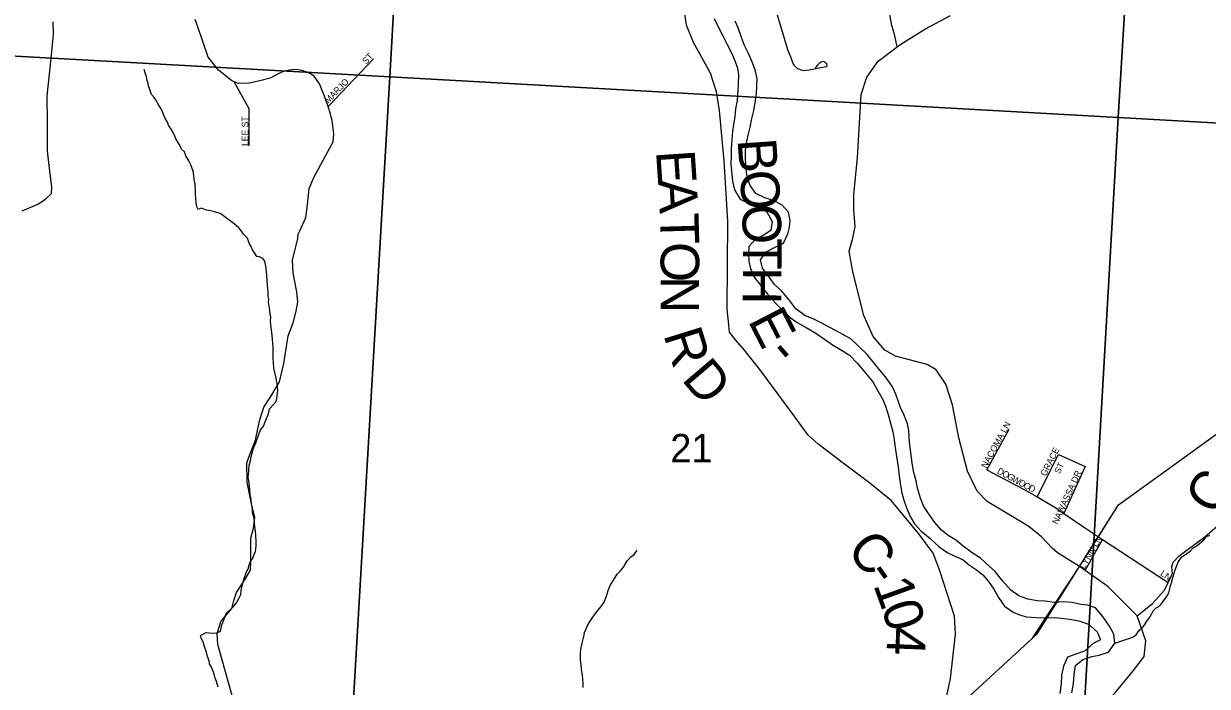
# Model space of a CAD drawing. Extents: x 0 to 34, y 0 to 22.
# Drawn here: x 4.174 to 5.915, y 17.152 to 18.127 of the extents above; entities that cross this region are included whole.
import ezdxf

# ---------------------------------------------------------------- set-up
doc = ezdxf.new("R2010")
doc.units = 0
for name, color, linetype in [('GM_P_State_Alignment', 7, 'Continuous'), ('GM_X_County_Road', 7, 'Continuous'), ('GM_X_County_Road_Text', 7, 'Continuous'), ('GM_X_Major_River', 7, 'Continuous'), ('GM_X_Minor_River', 7, 'Continuous'), ('GM_X_Section', 7, 'Continuous'), ('GM_X_Section_Text', 7, 'Continuous'), ('GM_X_Township_Road', 7, 'Continuous'), ('GM_X_Township_Subdivision', 7, 'Continuous'), ('GM_X_Township_Subdivision_Text', 7, 'Continuous'), ('SH_Data', 7, 'Continuous')]:
    doc.layers.add(name, color=color, linetype=linetype)

msp = doc.modelspace()

# ---------------------------------------------------------------- linework, layer by layer
at = {"layer": 'GM_P_State_Alignment'}
for points in [[(5.7539, 17.3702), (5.755, 17.3719), (5.7846, 17.4188), (6.0315, 17.5972), (6.2517, 17.7771), (6.3812, 17.906), (6.3923, 17.9142), (6.5211, 17.9881), (6.5265, 17.9911), (6.5405, 17.99), (6.6417, 17.9816), (6.6804, 17.9677), (6.7928, 17.9227), (6.8111, 17.9139), (6.95, 17.8445), (6.9564, 17.8413), (6.9734, 17.8302), (7.1338, 17.7232), (7.4175, 17.6454), (7.7316, 17.5623), (7.9253, 17.5014), (8.1533, 17.4614), (8.4655, 17.4165), (8.5004, 17.4073)], [(5.5533, 17.1267), (5.6581, 17.2228), (5.6649, 17.2291), (5.7272, 17.3279), (5.7539, 17.3702)]]:
    msp.add_lwpolyline(points, dxfattribs=at)
at = {"layer": 'GM_X_County_Road'}
for points in [[(5.2113, 17.6825), (5.2111, 17.6838), (5.2088, 17.7069), (5.2099, 17.836), (5.2042, 17.9248), (5.1973, 17.9992), (5.1928, 18.0265), (5.1844, 18.0542), (5.159, 18.099), (5.1491, 18.1244), (5.1438, 18.1574)], [(5.7687, 17.2984), (5.7353, 17.3221), (5.7272, 17.3279), (5.6949, 17.348), (5.687, 17.3548), (5.6714, 17.3715), (5.6528, 17.3867), (5.5914, 17.4235), (5.5766, 17.4387), (5.5622, 17.4683), (5.5497, 17.5176), (5.5402, 17.5658), (5.5307, 17.5962), (5.5163, 17.6175), (5.503, 17.6254), (5.4564, 17.6376), (5.4408, 17.6463), (5.4234, 17.6664), (5.4097, 17.6975), (5.3934, 17.7617), (5.3881, 17.792), (5.3937, 17.8114), (5.3971, 17.8285), (5.3949, 17.8531), (5.3949, 17.8748), (5.4005, 17.9298), (5.4058, 18.0228), (5.4141, 18.0483), (5.4311, 18.0714), (5.4591, 18.0925), (5.4645, 18.0965), (5.4994, 18.1185), (5.5373, 18.1387)], [(4.1716, 17.8515), (4.1944, 17.861), (4.2057, 17.8686), (4.2144, 17.877), (4.2151, 17.8865), (4.2116, 17.9137), (4.2087, 17.9395), (4.2085, 17.9814), (4.208, 18.0205), (4.2133, 18.0664), (4.2174, 18.1102), (4.2168, 18.1297)], [(5.8626, 17.3148), (5.864, 17.3177), (5.8632, 17.3276), (5.8651, 17.3344), (5.8738, 17.3436), (5.9117, 17.3717), (5.9375, 17.3945), (5.9761, 17.4302), (6.0004, 17.4477), (6.0284, 17.4572), (6.0584, 17.4599), (6.1057, 17.4713), (6.1402, 17.4976), (6.1663, 17.5242), (6.1951, 17.5504), (6.2021, 17.56), (6.2341, 17.6043), (6.269, 17.659), (6.2947, 17.6936), (6.3364, 17.7381), (6.3883, 17.7909), (6.4224, 17.8395), (6.444, 17.868), (6.4684, 17.8891)], [(5.5038, 17.0326), (5.5037, 17.0328), (5.4991, 17.0444), (5.5018, 17.0641), (5.5221, 17.1096), (5.5306, 17.131), (5.5374, 17.1633), (5.5449, 17.2286), (5.543, 17.2548), (5.5217, 17.3217), (5.5119, 17.3479), (5.4906, 17.3763), (5.4504, 17.4245), (5.4186, 17.4507), (5.3757, 17.4833), (5.342, 17.5084), (5.3279, 17.5213), (5.3082, 17.5482), (5.2581, 17.6162), (5.2342, 17.6462), (5.221, 17.6617), (5.2123, 17.6727), (5.2113, 17.6825)], [(5.8121, 17.2554), (5.8345, 17.2736), (5.8523, 17.293), (5.8577, 17.3045), (5.8626, 17.3148)], [(5.5775, 16.8401), (5.5775, 16.8401), (5.5917, 16.8644), (5.6126, 16.8982), (5.6436, 16.9499), (5.6671, 16.9898), (5.6894, 17.0263), (5.7152, 17.0673), (5.7402, 17.0981), (5.7815, 17.1445), (5.8068, 17.1749), (5.8224, 17.1954), (5.8246, 17.2189), (5.8121, 17.2554), (5.7704, 17.2971), (5.7687, 17.2983), (5.7687, 17.2984)]]:
    msp.add_lwpolyline(points, dxfattribs=at)
at = {"layer": 'GM_X_Major_River'}
for points in [[(5.1898, 18.1342), (5.1956, 18.1221), (5.2024, 18.1088), (5.2085, 18.0963), (5.215, 18.0838), (5.2207, 18.0713), (5.2237, 18.0611), (5.2253, 18.0516), (5.2249, 18.0384), (5.2242, 18.0285), (5.2235, 18.0137), (5.2212, 18.0016), (5.2198, 17.9898), (5.2179, 17.9784), (5.2168, 17.9682), (5.2157, 17.9564), (5.2146, 17.9431), (5.2146, 17.9325), (5.2143, 17.92), (5.2151, 17.9101), (5.2166, 17.895), (5.2197, 17.8821), (5.2277, 17.8688), (5.2402, 17.8628), (5.2531, 17.8579), (5.2671, 17.85), (5.2747, 17.8356), (5.2732, 17.8227), (5.2619, 17.815), (5.2513, 17.8105), (5.2407, 17.799), (5.24, 17.7884), (5.2408, 17.7767), (5.2431, 17.7664), (5.2484, 17.7539), (5.2587, 17.741), (5.2682, 17.7289), (5.28, 17.7157), (5.2895, 17.7058)], [(5.24, 18.0828), (5.2342, 18.0949), (5.23, 18.1063), (5.2251, 18.1207), (5.2205, 18.1305)], [(5.3799, 17.6689), (5.369, 17.675), (5.3588, 17.6802), (5.3489, 17.6855), (5.3361, 17.6919), (5.3232, 17.6972), (5.3099, 17.7074), (5.2993, 17.7211), (5.2886, 17.7335), (5.2784, 17.743), (5.2708, 17.7532), (5.2605, 17.7669), (5.2578, 17.7794), (5.2661, 17.7911), (5.2786, 17.7976), (5.2918, 17.8037), (5.2978, 17.8178), (5.3005, 17.8273), (5.3012, 17.8371), (5.2989, 17.8493), (5.2894, 17.8603), (5.2769, 17.8667), (5.264, 17.8704), (5.2507, 17.8768), (5.2424, 17.8886), (5.2382, 17.9011), (5.2366, 17.9132), (5.2358, 17.928), (5.2358, 17.9409), (5.2373, 17.9515), (5.2403, 17.9648), (5.2425, 17.9743), (5.2451, 17.9872), (5.2478, 17.999), (5.25, 18.0104), (5.2518, 18.024), (5.2526, 18.0343), (5.2529, 18.0456), (5.2499, 18.0589), (5.2449, 18.0714), (5.24, 18.0828)], [(5.2895, 17.7058), (5.3012, 17.6945), (5.3118, 17.6869), (5.3251, 17.6798), (5.3391, 17.6715), (5.3517, 17.6628), (5.3638, 17.6541), (5.3755, 17.6473), (5.3888, 17.639), (5.4002, 17.6272), (5.4108, 17.6144), (5.423, 17.6), (5.4302, 17.5867), (5.4378, 17.5739), (5.4416, 17.564), (5.4455, 17.5519), (5.4489, 17.539), (5.4527, 17.5261), (5.4543, 17.5143), (5.4558, 17.5033), (5.4578, 17.4897), (5.4601, 17.4745), (5.462, 17.4612), (5.4636, 17.4476), (5.4655, 17.4366), (5.4685, 17.4256), (5.472, 17.4157), (5.4773, 17.4028), (5.4842, 17.3907), (5.4936, 17.3805), (5.5069, 17.3699), (5.5206, 17.357), (5.5335, 17.3483), (5.546, 17.3423), (5.5558, 17.3378), (5.5653, 17.3302), (5.5756, 17.3234), (5.5851, 17.3158), (5.5934, 17.306), (5.601, 17.2946), (5.6082, 17.2825), (5.617, 17.2696), (5.6295, 17.2609), (5.639, 17.2568), (5.6492, 17.2542), (5.6632, 17.2531), (5.6765, 17.2527), (5.6901, 17.2528), (5.6999, 17.252), (5.7128, 17.2506), (5.7264, 17.2483), (5.7405, 17.243), (5.753, 17.2317), (5.7583, 17.2203), (5.7474, 17.2146), (5.7345, 17.2036), (5.7217, 17.1993), (5.7096, 17.1947), (5.7035, 17.1814), (5.7009, 17.1682), (5.7002, 17.1552), (5.6984, 17.1412)], [(5.7158, 17.1424), (5.7184, 17.1561), (5.7195, 17.169), (5.7213, 17.1823), (5.7323, 17.191), (5.7455, 17.1956), (5.7561, 17.1975), (5.7697, 17.2018), (5.7792, 17.2151), (5.7776, 17.2287), (5.7715, 17.2401), (5.7616, 17.2545), (5.7506, 17.2674), (5.7389, 17.2711), (5.729, 17.2722), (5.7165, 17.2752), (5.7029, 17.276), (5.6904, 17.2752), (5.6764, 17.277), (5.665, 17.2777), (5.651, 17.28), (5.6378, 17.2849), (5.626, 17.2932), (5.6142, 17.3064), (5.6032, 17.3208), (5.5937, 17.3292), (5.5816, 17.3401), (5.5691, 17.3484), (5.5562, 17.3579), (5.5463, 17.3662), (5.5338, 17.3738), (5.5239, 17.3817), (5.5144, 17.3927), (5.5049, 17.4059), (5.4981, 17.4162), (5.4931, 17.4287), (5.4889, 17.4435), (5.4866, 17.4541), (5.4836, 17.4666), (5.4809, 17.4802), (5.4793, 17.4924), (5.4774, 17.5068), (5.4766, 17.5178), (5.4762, 17.528), (5.4739, 17.5379), (5.4686, 17.5516), (5.464, 17.5622), (5.4605, 17.572), (5.4567, 17.5815), (5.4518, 17.5925), (5.4415, 17.6073), (5.4332, 17.6171), (5.4248, 17.6273), (5.4149, 17.6402), (5.4013, 17.653), (5.3906, 17.6629), (5.3812, 17.6682), (5.3799, 17.6689)]]:
    msp.add_lwpolyline(points, dxfattribs=at)
at = {"layer": 'GM_X_Minor_River'}
for points in [[(4.4103, 17.9382), (4.4058, 17.9421), (4.4032, 17.9482), (4.3981, 17.9563), (4.3952, 17.9639), (4.3908, 17.9716), (4.3874, 17.9766), (4.3845, 17.9827), (4.382, 17.9873), (4.3794, 17.9931), (4.3769, 18), (4.3739, 18.0042), (4.371, 18.0092), (4.3688, 18.0134), (4.3654, 18.018), (4.3617, 18.0226), (4.3592, 18.0299), (4.3574, 18.0352), (4.3567, 18.039), (4.3553, 18.0432), (4.3542, 18.0486), (4.3525, 18.0547), (4.351, 18.0593)], [(4.5156, 17.3584), (4.5157, 17.3637), (4.5152, 17.3751), (4.5145, 17.3793), (4.5139, 17.3873), (4.5132, 17.3911), (4.5126, 17.3991), (4.5104, 17.4075), (4.5101, 17.4117), (4.5088, 17.4209), (4.5081, 17.4266), (4.5071, 17.4342), (4.5065, 17.4414), (4.5058, 17.4464), (4.5048, 17.4548), (4.5041, 17.4589), (4.5046, 17.4635), (4.5047, 17.4692), (4.5056, 17.4772), (4.5068, 17.4817), (4.5085, 17.4897), (4.5093, 17.4934), (4.5113, 17.5006), (4.5129, 17.5048), (4.5153, 17.5101), (4.5165, 17.5146), (4.5185, 17.5199), (4.522, 17.529), (4.5263, 17.5346), (4.5287, 17.541), (4.531, 17.5459), (4.533, 17.5501), (4.5342, 17.5553), (4.5355, 17.5599), (4.5412, 17.5663), (4.5451, 17.5707), (4.5459, 17.5753), (4.5472, 17.5833), (4.5477, 17.587), (4.5467, 17.5966), (4.545, 17.605), (4.5418, 17.6198), (4.5412, 17.6278), (4.5409, 17.6347), (4.5407, 17.6426), (4.5405, 17.6518), (4.5402, 17.6556), (4.5395, 17.6624), (4.5386, 17.6727), (4.5376, 17.6799), (4.5372, 17.6841), (4.537, 17.6891), (4.5371, 17.6952), (4.5364, 17.699), (4.5357, 17.7051), (4.534, 17.7169), (4.5341, 17.721), (4.5334, 17.7268), (4.5332, 17.7332), (4.5326, 17.7412), (4.532, 17.75), (4.5313, 17.7553), (4.531, 17.7621), (4.53, 17.7701), (4.5283, 17.7774), (4.5257, 17.7812), (4.5208, 17.7836), (4.5167, 17.7844), (4.513, 17.7894), (4.5104, 17.794), (4.5086, 17.7979), (4.5052, 17.8036), (4.5027, 17.8113), (4.4971, 17.817), (4.4942, 17.8217), (4.4901, 17.8263), (4.4834, 17.8325), (4.4793, 17.8352), (4.4726, 17.8403), (4.4669, 17.8445), (4.4625, 17.8473), (4.4572, 17.8489), (4.4527, 17.8505), (4.4485, 17.8513), (4.4428, 17.8526), (4.4387, 17.8538), (4.4349, 17.8553), (4.4304, 17.8535), (4.4285, 17.8574), (4.4275, 17.8638), (4.4269, 17.8707), (4.4262, 17.8745), (4.4263, 17.8806), (4.4261, 17.8905), (4.4243, 17.8977), (4.4234, 17.9076), (4.4212, 17.9152), (4.4198, 17.9191), (4.4165, 17.9252), (4.4124, 17.9325), (4.4103, 17.9382)], [(5.7792, 17.2151), (5.7951, 17.2208), (5.8, 17.2222), (5.8061, 17.2248), (5.8107, 17.2274), (5.8135, 17.2319), (5.8166, 17.2356), (5.8204, 17.2386), (5.8231, 17.2427), (5.8262, 17.2476), (5.8305, 17.2536), (5.8332, 17.2578), (5.8356, 17.2627), (5.8398, 17.2672), (5.844, 17.269), (5.8475, 17.2727), (5.851, 17.278), (5.8561, 17.2848), (5.8584, 17.2893), (5.8596, 17.2934), (5.8609, 17.2999), (5.8628, 17.3048), (5.8637, 17.3086), (5.8677, 17.323), (5.8705, 17.3294), (5.8728, 17.3354), (5.8775, 17.3422), (5.8833, 17.3459), (5.8905, 17.3511), (5.8944, 17.3556), (5.8982, 17.3574), (5.9036, 17.3619), (5.9101, 17.3671), (5.9136, 17.3716), (5.919, 17.3742)], [(4.4597, 17.1503), (4.4572, 17.159), (4.4554, 17.1636), (4.4544, 17.1675), (4.4529, 17.1724), (4.45, 17.1797), (4.4471, 17.1847), (4.4464, 17.1893), (4.4442, 17.1958), (4.4428, 17.2019), (4.4403, 17.2091), (4.4371, 17.2183), (4.4349, 17.2225), (4.4338, 17.2267), (4.4422, 17.2308), (4.446, 17.2307), (4.452, 17.2302), (4.4577, 17.2305), (4.4631, 17.2331), (4.4643, 17.2372), (4.4651, 17.2422), (4.4667, 17.2459), (4.4699, 17.255), (4.4719, 17.2599), (4.478, 17.2648), (4.4834, 17.2704), (4.4873, 17.2756), (4.4908, 17.282), (4.4932, 17.2869), (4.4937, 17.2926), (4.4949, 17.2994), (4.4978, 17.3104), (4.5013, 17.3202), (4.5045, 17.3251), (4.5049, 17.3293), (4.5073, 17.3354), (4.5108, 17.3402), (4.5124, 17.3448), (4.5147, 17.3501), (4.5156, 17.3584)], [(4.9969, 17.1498), (4.9966, 17.1548), (4.9963, 17.1632), (4.996, 17.1674), (4.9954, 17.1715), (4.9943, 17.1765), (4.9937, 17.1837), (4.993, 17.1902), (4.9931, 17.1955), (4.9928, 17.2009), (4.9933, 17.2058), (4.9954, 17.2153), (4.9982, 17.227), (4.999, 17.2312), (5.001, 17.2349), (5.0026, 17.2402), (5.0053, 17.2447), (5.01, 17.2519), (5.0162, 17.2602), (5.0228, 17.2688), (5.0275, 17.2755), (5.0314, 17.2842), (5.0342, 17.2944), (5.037, 17.3009), (5.0401, 17.3054), (5.0468, 17.317), (5.0514, 17.3211), (5.056, 17.3271), (5.0587, 17.3313), (5.0619, 17.3369), (5.0669, 17.3425), (5.0719, 17.3459), (5.0762, 17.3519)]]:
    msp.add_lwpolyline(points, dxfattribs=at)
at = {"layer": 'GM_X_Section'}
for points in [[(3.6864, 19.1354), (4.7704, 19.0729), (4.7124, 18.0487), (3.6288, 18.1086)], [(5.8458, 19.0101), (5.784, 17.9889), (4.7124, 18.0487), (4.7704, 19.0729)], [(6.9173, 18.9472), (6.8533, 17.9287), (5.784, 17.9889), (5.8458, 19.0101)], [(3.6288, 18.1086), (4.7124, 18.0487), (4.6537, 17.0401), (3.5685, 17.0999)], [(4.7124, 18.0487), (5.784, 17.9889), (5.726, 16.9791), (4.6537, 17.0401)], [(5.784, 17.9889), (6.8533, 17.9287), (6.7904, 16.9223), (5.726, 16.9791)]]:
    msp.add_lwpolyline(points, close=True, dxfattribs=at)
at = {"layer": 'GM_X_Township_Road'}
for points in [[(4.5148, 17.5144), (4.5152, 17.5163), (4.5204, 17.5424), (4.5268, 17.5626), (4.5374, 17.5781), (4.5502, 17.5998), (4.5562, 17.6268), (4.5626, 17.6674), (4.5701, 17.6868), (4.5746, 17.7039), (4.5772, 17.7172), (4.5757, 17.732), (4.5703, 17.7601), (4.5691, 17.7787), (4.5768, 17.8106), (4.5773, 17.817), (4.5803, 17.823), (4.5887, 17.8414), (4.5912, 17.8603), (4.5937, 17.8842), (4.6007, 17.9006), (4.6143, 17.9261), (4.6288, 17.953), (4.6302, 17.9647), (4.6273, 17.9841), (4.624, 17.9973), (4.6215, 18.0047), (4.6161, 18.0202), (4.6089, 18.0383), (4.6012, 18.0495), (4.5922, 18.055), (4.583, 18.058), (4.5748, 18.0595), (4.5683, 18.0589), (4.5569, 18.0567), (4.5489, 18.0535), (4.5363, 18.0468), (4.5213, 18.0426), (4.5054, 18.0391), (4.4895, 18.0389), (4.4835, 18.0413), (4.4793, 18.043), (4.4604, 18.0583), (4.445, 18.0773), (4.4298, 18.1221), (4.4257, 18.1331)], [(4.4809, 17.1363), (4.4595, 17.2134), (4.4583, 17.229), (4.4635, 17.2472), (4.4798, 17.2662), (4.4828, 17.278), (4.4866, 17.2898), (4.5005, 17.3111), (4.5073, 17.3229), (4.5077, 17.335), (4.5076, 17.3555), (4.5076, 17.37), (4.5117, 17.3844), (4.5136, 17.4004), (4.509, 17.4201), (4.5024, 17.452), (4.502, 17.4805), (4.5073, 17.4953), (4.5144, 17.5124), (4.5148, 17.5144)]]:
    msp.add_lwpolyline(points, dxfattribs=at)
at = {"layer": 'GM_X_Township_Subdivision'}
for points in [[(5.4591, 18.0925), (5.4555, 18.1088), (5.4528, 18.1178), (5.451, 18.1241), (5.4456, 18.1533)], [(5.2805, 18.1461), (5.2895, 18.1151), (5.2976, 18.089), (5.303, 18.0755), (5.3059, 18.0672), (5.3079, 18.0646), (5.312, 18.061), (5.3147, 18.0597), (5.3174, 18.0588), (5.3214, 18.0579), (5.3295, 18.0588), (5.3367, 18.0601), (5.3516, 18.0633), (5.3552, 18.0637), (5.3561, 18.0647), (5.3556, 18.0665), (5.3552, 18.0678), (5.3538, 18.0687), (5.352, 18.0705), (5.3498, 18.071), (5.3471, 18.0701), (5.3444, 18.0686), (5.3415, 18.0657), (5.3385, 18.0624), (5.3385, 18.0601)], [(4.6215, 18.0047), (4.6881, 18.0752)], [(4.5055, 17.9468), (4.5055, 18.0015), (4.4835, 18.0413)], [(5.5909, 17.4702), (5.6239, 17.5302)], [(5.6647, 17.4307), (5.6965, 17.4931)], [(5.6965, 17.4931), (5.7354, 17.4753), (5.7043, 17.4062)], [(5.5909, 17.4702), (5.645, 17.4421), (5.6647, 17.4307), (5.691, 17.4154), (5.7043, 17.4062), (5.7358, 17.3845)], [(5.7358, 17.3845), (5.755, 17.3719), (5.7612, 17.3678), (5.8577, 17.3045)], [(5.7353, 17.3221), (5.7612, 17.3678)]]:
    msp.add_lwpolyline(points, dxfattribs=at)
at = {"layer": 'SH_Data'}
msp.add_lwpolyline([(4.3712, 16.3386), (4.4624, 16.5517), (4.5028, 16.6273), (4.6421, 16.7261), (4.7521, 16.7559), (4.9193, 16.8683), (5.0406, 16.9393), (5.2028, 16.9908), (5.3394, 17.0347), (5.5221, 17.1096), (5.5533, 17.1267), (5.6581, 17.2228), (5.7272, 17.3279), (5.7846, 17.4188), (6.0315, 17.5972)], dxfattribs=at)

# ---------------------------------------------------------------- texts
at = {"layer": 'GM_X_County_Road_Text'}
for s, rotation, p in [('B', 274.0273, (5.2239, 17.9564)), ('E', 273.8471, (5.104, 17.9393)), ('O', 273.7949, (5.2272, 17.9099)), ('A', 273.2219, (5.1069, 17.8971)), ('O', 271.8108, (5.2304, 17.8605)), ('T', 271.6759, (5.1097, 17.8476)), ('O', 269.8069, (5.1109, 17.8056)), ('T', 269.8286, (5.232, 17.8111)), ('N', 269.9811, (5.1107, 17.7554)), ('H', 269.7632, (5.2319, 17.7686)), ('E', 297.2536, (5.2386, 17.6899)), ('R', 287.296, (5.1145, 17.6694)), ('-', 310.6541, (5.2661, 17.6401)), ('D', 310.4016, (5.1403, 17.6031)), ('C', 57.4988, (5.9271, 17.4008)), ('C', 308.651, (5.383, 17.3524)), ('-', 305.3995, (5.4116, 17.3167)), ('1', 289.9135, (5.4233, 17.3012)), ('0', 287.3977, (5.435, 17.2689)), ('4', 267.7669, (5.4448, 17.2406))]:
    msp.add_text(s, height=0.0568, rotation=rotation, dxfattribs=at).set_placement(p)
at = {"layer": 'GM_X_Section_Text'}
msp.add_text('21', height=0.04186, rotation=0, dxfattribs=at).set_placement((5.125, 17.4813))
at = {"layer": 'GM_X_Township_Subdivision_Text'}
for s, rotation, p in [('ST', 47.4856, (4.6778, 18.0663)), ('MARJO', 45.8542, (4.622, 18.0088)), ('LEE ST', 90, (4.504, 17.9468)), ('NACOMA LN', 61.2814, (5.5901, 17.4718)), ('GRACE', 62.8787, (5.6775, 17.4601)), ('D', 331.1543, (5.605, 17.4658)), ('O', 331.1566, (5.6123, 17.4618)), ('NAWASSA DR', 65.4013, (5.695, 17.3892)), ('ST', 63.4349, (5.6979, 17.4636)), ('G', 331.1566, (5.6196, 17.4578)), ('W', 331.1493, (5.6269, 17.4538)), ('O', 331.2616, (5.6364, 17.4485)), ('O', 332.6744, (5.6439, 17.4444)), ('D', 333.4028, (5.6514, 17.4405)), ('LYNN LN', 60.0194, (5.7343, 17.3235)), ('LN', 325.4967, (5.8451, 17.3157))]:
    msp.add_text(s, height=0.00947, rotation=rotation, dxfattribs=at).set_placement(p)

doc.saveas('drawing.dxf')
